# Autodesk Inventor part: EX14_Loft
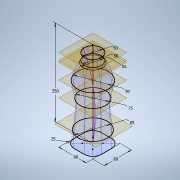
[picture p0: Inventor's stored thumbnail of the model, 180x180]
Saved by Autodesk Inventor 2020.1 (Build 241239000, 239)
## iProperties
Created: 2019-10
Part Number: EX14_Loft
Material: Glass
Document SubType Name: Modeling
Designer: Synergysoft Dell02
Density: 2.18 g/cm^3
Appearance: Clear - Blue
Author: Synergysoft Dell02
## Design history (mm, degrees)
sketch "Sketch1"
  geometry: L1 (15, 40)-(-15, 40); L2 (-40, 15)-(-40, -15); L3 (-15, -40)-(15, -40); L4 (40, -15)-(40, 15); L5 (40, 40)-(-40, -40); L6 (-40, 40)-(40, -40); A1 r 25 centre (15, 15) between (40, 15) and (15, 40); A2 r 25 centre (15, -15) between (15, -40) and (40, -15); A3 r 25 centre (-15, -15) between (-40, -15) and (-15, -40); A4 r 25 centre (-15, 15) between (-15, 40) and (-40, 15); 1 further point
  constraints: 12 end point, 8 point on circle, 8 point on line, 8 tangent, 4 centre point, 3 equal radius, 2 midpoint, 2 parallel, 1 horizontal, 1 perpendicular
  dimensions: "d0" = 80 distance of L6.end L5.end; "d1" = 80 distance of L5.end L6.start; "d2" = 25 radius of A1
workplane "Work Plane1"
sketch "Sketch2"
  geometry: C1 r 42.5 at (0, 0); 1 further point
  constraints: 1 centre point, 1 coincident
  dimensions: "d4" = 85 diameter of C1
workplane "Work Plane2"
sketch "Sketch3"
  geometry: C1 r 37.5 at (0, 0); 1 further point
  constraints: 1 centre point, 1 coincident
  dimensions: "d6" = 75 diameter of C1
workplane "Work Plane3"
sketch "Sketch4"
  geometry: C1 r 45 at (0, 0); 1 further point
  constraints: 1 centre point, 1 coincident
  dimensions: "d8" = 90 diameter of C1
workplane "Work Plane4"
sketch "Sketch5"
  geometry: C1 r 27.5 at (0, 0); 1 further point
  constraints: 1 centre point, 1 coincident
  dimensions: "d10" = 55 diameter of C1
workplane "Work Plane5"
sketch "Sketch9"
  geometry: C1 r 25 at (0, 0); 1 further point
  constraints: 1 centre point, 1 coincident
  dimensions: "d31" = 50 diameter of C1
workplane "Work Plane6"
sketch "Sketch10"
  geometry: C1 r 25 at (0, 0); 1 further point
  constraints: 1 centre point, 1 coincident
  dimensions: "d33" = 50 diameter of C1
node "3D Sketch1" dims "d48" = 250
sketch "Sketch7"
  geometry: L1 (0, 0)-(22.159, 139.709); L2 (22.159, 139.709)-(-29.767, 228.961)
  constraints: 3 other
loft "Loft4" dims "d53" = 0, "d54" = 90 deg, "d55" = 0, "d56" = 90 deg, "d57" = 0, "d58" = 90 deg, "d59" = 0, "d60" = 90 deg, "d61" = 0, "d62" = 90 deg, "d63" = 0, "d64" = 90 deg, "d65" = 0, "d66" = 90 deg
loft "Loft3" dims "d34" = 0, "d35" = 90 deg, "d36" = 0, "d37" = 90 deg, "d38" = 0, "d39" = 90 deg, "d40" = 0, "d41" = 90 deg, "d42" = 0, "d43" = 90 deg, "d44" = 0, "d45" = 90 deg, "d46" = 0, "d47" = 90 deg, "d51" = 0, "d52" = 90 deg
loft "Loft5" dims "d67" = 0, "d68" = 90 deg, "d69" = 0, "d70" = 90 deg, "d71" = 0, "d72" = 90 deg
loft "Loft6" dims "d73" = 0, "d74" = 90 deg, "d75" = 0, "d76" = 90 deg, "d77" = 0, "d78" = 90 deg, "d79" = 0, "d80" = 90 deg, "d81" = 0, "d82" = 0, "d83" = 586.34954, "d84" = 10, "d85" = 115, "d86" = 5.60976, "d87" = 441.78647, "d88" = 10, "d89" = 205, "d90" = 10, "d91" = 237.58294, "d92" = 10, "d93" = 123, "d94" = 6, "d95" = 520, "d96" = 11.21129
body "Solid1"
body "Solid2"
body "Solid3"
body "Solid4"
body "Solid5"
other parameters: "d3" = 35, "d7" = 45, "d9" = 45, "d11" = 5
